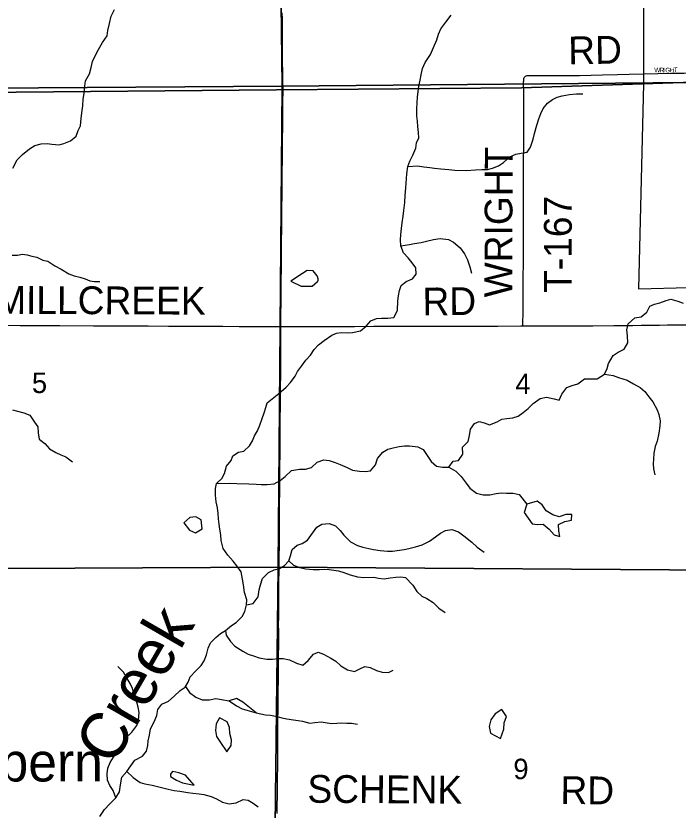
# Model space of a CAD drawing. Extents: x 0 to 1391, y -24 to 440.
# Drawn here: x 416.5 to 443.6, y 299.64 to 332.13 of the extents above; entities that cross this region are included whole.
import ezdxf

# ---------------------------------------------------------------- set-up
doc = ezdxf.new("R2010")
doc.units = 0
for name, color, linetype in [('GM_X_City_Street', 7, 'Continuous'), ('GM_X_City_Street_Text', 7, 'Continuous'), ('GM_X_Corporation', 7, 'Continuous'), ('GM_X_County_Road', 7, 'Continuous'), ('GM_X_County_Road_Text', 7, 'Continuous'), ('GM_X_Minor_Lake', 7, 'Continuous'), ('GM_X_Minor_River', 7, 'Continuous'), ('GM_X_Minor_River_Text', 7, 'Continuous'), ('GM_X_Section', 7, 'Continuous'), ('GM_X_Section_Text', 7, 'Continuous'), ('GM_X_Township', 7, 'Continuous'), ('GM_X_Township_Road', 7, 'Continuous'), ('GM_X_Township_Road_Text', 7, 'Continuous'), ('GM_X_Unincorporated_Text', 7, 'Continuous')]:
    doc.layers.add(name, color=color, linetype=linetype)

msp = doc.modelspace()

# ---------------------------------------------------------------- linework, layer by layer
at = {"layer": 'GM_X_City_Street'}
msp.add_lwpolyline([(442.19, 329.762), (442.767, 329.777), (443.327, 329.783), (443.836, 329.79), (444.271, 329.796), (444.88, 329.802), (445.689, 329.801), (445.987, 329.805), (446.099, 329.813), (446.184, 329.83), (446.255, 329.854), (446.299, 329.876), (446.351, 329.91), (446.408, 329.958), (446.475, 330.031), (446.574, 330.16), (447.022, 330.771), (447.05, 330.799), (447.082, 330.824), (447.146, 330.858)], dxfattribs=at)
at = {"layer": 'GM_X_Corporation'}
msp.add_lwpolyline([(442.179, 333.534), (442.187, 329.348), (441.975, 320.968), (444.035, 321.013)], dxfattribs=at)
at = {"layer": 'GM_X_County_Road'}
for points in [[(415.038, 319.479), (415.24, 319.478), (415.7, 319.473), (416.681, 319.468), (417.464, 319.464), (418.297, 319.459), (419.676, 319.452), (420.559, 319.449), (421.329, 319.451), (421.913, 319.449), (422.746, 319.442), (422.97, 319.442), (423.193, 319.442), (423.628, 319.441), (424.287, 319.437), (424.97, 319.431), (425.641, 319.424), (426.263, 319.417), (427.341, 319.416)], [(427.341, 319.416), (427.518, 319.416), (428.027, 319.418), (428.859, 319.416), (429.717, 319.416), (430.351, 319.421), (431.134, 319.431), (431.793, 319.434), (432.053, 319.434), (432.513, 319.434), (433.419, 319.437), (433.729, 319.436), (434.202, 319.438), (434.985, 319.439), (435.606, 319.438), (436.227, 319.442), (437.16, 319.444), (437.251, 319.445)], [(437.251, 319.445), (437.756, 319.446), (438.378, 319.452), (439.856, 319.454), (440.105, 319.452), (440.962, 319.46), (441.31, 319.463), (441.745, 319.467), (442.093, 319.471), (442.838, 319.48), (443.161, 319.484), (443.533, 319.489), (444.006, 319.488), (444.553, 319.492), (445.087, 319.491), (445.696, 319.493), (446.18, 319.49), (446.553, 319.491), (447.137, 319.491)]]:
    msp.add_lwpolyline(points, dxfattribs=at)
at = {"layer": 'GM_X_Minor_Lake'}
for points in [[(428.826, 321.491), (428.663, 321.699), (428.42, 321.711), (428.227, 321.594), (427.745, 321.278)], [(428.837, 321.256), (428.841, 321.258), (428.844, 321.26), (428.847, 321.263), (428.85, 321.266), (428.852, 321.269), (428.855, 321.272), (428.857, 321.276), (428.86, 321.279), (428.862, 321.283), (428.864, 321.288), (428.865, 321.292), (428.867, 321.297), (428.868, 321.302), (428.869, 321.307), (428.87, 321.312), (428.871, 321.318), (428.871, 321.324), (428.872, 321.33), (428.872, 321.336), (428.872, 321.342), (428.871, 321.348), (428.871, 321.355), (428.87, 321.361), (428.869, 321.368), (428.868, 321.375), (428.867, 321.382), (428.865, 321.389), (428.864, 321.396), (428.862, 321.403), (428.86, 321.411), (428.858, 321.418), (428.855, 321.425), (428.853, 321.432), (428.85, 321.44), (428.847, 321.447), (428.844, 321.455), (428.841, 321.462), (428.837, 321.469), (428.834, 321.476), (428.83, 321.484), (428.826, 321.491)], [(427.745, 321.278), (428.172, 321.073), (428.362, 321.069), (428.621, 321.071), (428.837, 321.256)], [(438.704, 311.326), (438.963, 311.448), (439.23, 311.503), (439.256, 311.73), (439.006, 311.735), (438.73, 311.642), (438.466, 311.723), (438.203, 311.88), (438.04, 312.134), (437.837, 312.274), (437.404, 312.157)], [(437.404, 312.157), (437.297, 311.816), (437.46, 311.578), (437.63, 311.347), (437.85, 311.32), (438.071, 311.338), (438.326, 311.136), (438.527, 310.897), (438.754, 310.831), (438.72, 311.067), (438.704, 311.326)], [(424.128, 311.139), (424.087, 311.519), (423.861, 311.637), (423.617, 311.604), (423.374, 311.397)], [(423.374, 311.397), (423.6, 311.09), (423.849, 310.978), (424.128, 311.139)], [(426.335, 303.617), (425.786, 304.062), (425.522, 304.203), (425.223, 304.113)], [(425.223, 304.113), (425.524, 303.901), (425.766, 303.789), (426.335, 303.617)], [(436.391, 303.762), (436.108, 303.579), (435.929, 303.333), (435.871, 303.054), (435.927, 302.788), (436.334, 302.568)], [(436.334, 302.568), (436.469, 302.951), (436.482, 303.208), (436.578, 303.471), (436.391, 303.762)], [(424.83, 303.419), (424.698, 303.168), (424.67, 302.896), (424.711, 302.645), (424.867, 302.407), (425.133, 302.023)], [(425.133, 302.023), (425.313, 302.277), (425.325, 302.519), (425.253, 302.77), (425.235, 303.013), (425.148, 303.257), (424.83, 303.419)], [(422.922, 301.214), (422.897, 301.211), (422.827, 301.116), (422.826, 301.02)], [(423.79, 300.658), (423.444, 301.074), (423.172, 301.163), (422.922, 301.214)], [(422.826, 301.02), (423.076, 300.863), (423.325, 300.759), (423.79, 300.658)]]:
    msp.add_lwpolyline(points, dxfattribs=at)
at = {"layer": 'GM_X_Minor_River'}
for points in [[(416.381, 325.903), (416.55, 326.235), (416.771, 326.46), (417.053, 326.685), (417.282, 326.819), (417.54, 326.9), (417.776, 326.906), (417.973, 326.874), (418.269, 326.856), (418.467, 326.908), (418.741, 327.019), (418.969, 327.206), (419.054, 327.433), (419.146, 327.629), (419.171, 327.932), (419.203, 328.167), (419.234, 328.447), (419.251, 328.72), (419.29, 328.947), (419.322, 329.257), (419.346, 329.469), (419.507, 329.756), (419.585, 330.013), (419.632, 330.255), (419.747, 330.489), (419.877, 330.746), (420.046, 331.04), (420.23, 331.311), (420.269, 331.523), (420.331, 331.81), (420.401, 332.113), (420.539, 332.385)], [(430.829, 319.435), (431.03, 319.651), (431.26, 319.746), (431.466, 319.758), (431.717, 319.761), (431.969, 319.794), (432.119, 320.072), (432.125, 320.474), (432.151, 320.671), (432.193, 320.89), (432.273, 321.101), (432.466, 321.257), (432.727, 321.367), (432.875, 321.569), (432.871, 321.819), (432.715, 322.027), (432.551, 322.227), (432.356, 322.435), (432.254, 322.725), (432.243, 322.968), (432.254, 323.18), (432.281, 323.43), (432.308, 323.665), (432.351, 323.937), (432.378, 324.172), (432.413, 324.49), (432.433, 324.778), (432.454, 325.088), (432.465, 325.278), (432.502, 325.672), (432.545, 325.967), (432.624, 326.178), (432.743, 326.426), (432.862, 326.72), (432.896, 326.939), (432.983, 327.143), (432.972, 327.355), (432.953, 327.598), (432.934, 327.826), (432.907, 328.039), (432.904, 328.312), (432.916, 328.585), (432.935, 328.797), (432.988, 329.252), (433.046, 329.501), (433.08, 329.72), (433.137, 329.97), (433.248, 330.226), (433.467, 330.548), (433.593, 330.827), (433.728, 331.143), (433.793, 331.377), (433.895, 331.595), (434.09, 331.865), (434.316, 332.157)], [(432.545, 325.967), (432.941, 325.99), (433.192, 325.956), (433.435, 325.921), (433.625, 325.895), (433.891, 325.868), (434.21, 325.839), (434.469, 325.812), (434.94, 325.804), (435.306, 325.836), (435.565, 325.839), (435.794, 325.85), (436, 325.899), (436.246, 325.994), (436.453, 326.127), (436.716, 326.357), (436.954, 326.475), (437.183, 326.516), (437.42, 326.558), (437.553, 326.76), (437.665, 327.084), (437.722, 327.319), (437.819, 327.651), (437.9, 327.915), (437.979, 328.133), (438.082, 328.337), (438.253, 328.554), (438.461, 328.709), (438.653, 328.805), (438.852, 328.862), (439.15, 328.91), (439.44, 328.943), (439.706, 328.938)], [(432.254, 322.725), (432.605, 322.772), (432.812, 322.814), (433.079, 322.855), (433.301, 322.919), (433.591, 322.983), (433.858, 323.023), (434.2, 322.98), (434.404, 322.877), (434.682, 322.645), (434.86, 322.392), (434.978, 322.154), (435.072, 321.865), (435.144, 321.598)], [(416.353, 322.333), (416.566, 322.346), (416.771, 322.375), (416.961, 322.35), (417.158, 322.303), (417.363, 322.256), (417.605, 322.14), (417.802, 322.093), (418.09, 321.909), (418.347, 321.77), (418.665, 321.57), (418.885, 321.492), (419.12, 321.437), (419.332, 321.367), (419.529, 321.29), (419.718, 321.265), (419.931, 321.263)], [(434.212, 313.664), (434.391, 313.911), (434.612, 313.938), (434.792, 314.2), (434.781, 314.489), (435.014, 314.72), (435.056, 314.969), (435.106, 315.226), (435.27, 315.459), (435.461, 315.531), (435.658, 315.475), (435.885, 315.402), (436.192, 315.519), (436.384, 315.637), (436.59, 315.663), (436.834, 315.689), (437.049, 315.754), (437.257, 315.91), (437.457, 316.066), (437.667, 316.274), (437.959, 316.474), (438.212, 316.538), (438.522, 316.457), (438.727, 316.408), (438.838, 316.648), (439.048, 316.926), (439.27, 317.013), (439.492, 317.07), (439.77, 317.285), (440.036, 317.288), (440.287, 317.283), (440.58, 317.476), (440.691, 317.709), (440.747, 317.905), (440.943, 318.235), (441.143, 318.376), (441.397, 318.493), (441.546, 318.749), (441.528, 319.037), (441.501, 319.28), (441.559, 319.537), (441.822, 319.775), (442.081, 319.817), (442.313, 320.002), (442.446, 320.258), (442.638, 320.33), (442.845, 320.387), (443.113, 320.482), (443.304, 320.539), (443.584, 320.458), (443.804, 320.379)], [(419.939, 299.379), (420.126, 299.664), (420.351, 299.903), (420.591, 300.141), (420.74, 300.389), (420.775, 300.677), (420.842, 300.994), (421.043, 301.226), (421.207, 301.451), (421.371, 301.69), (421.678, 301.844), (421.841, 302.046), (421.899, 302.28), (421.917, 302.477), (421.974, 302.711), (422.009, 302.969), (422.159, 303.247), (422.27, 303.51), (422.312, 303.752), (422.468, 303.97), (422.744, 304.101), (422.976, 304.295), (423.223, 304.533), (423.431, 304.673), (423.556, 304.868), (423.629, 305.095), (423.861, 305.341), (424.086, 305.549), (424.211, 305.752), (424.298, 305.986), (424.364, 306.258), (424.459, 306.476), (424.684, 306.7), (424.877, 306.863), (425.077, 306.989), (425.324, 307.197), (425.516, 307.315), (425.764, 307.561), (425.866, 307.764), (425.94, 308.043), (425.951, 308.24), (425.849, 308.538), (425.808, 308.849), (425.774, 309.093), (425.719, 309.39), (425.548, 309.635), (425.398, 309.827), (425.167, 310.074), (424.988, 310.343), (424.895, 310.663), (424.884, 310.906), (424.849, 311.127), (424.815, 311.332), (424.795, 311.552), (424.784, 311.773), (424.75, 312.008), (424.693, 312.252), (424.667, 312.518), (424.664, 312.791), (424.713, 312.995), (424.922, 313.211), (425.032, 313.407), (425.121, 313.709), (425.315, 313.94), (425.379, 314.136), (425.61, 314.277), (425.832, 314.318), (426.064, 314.534), (426.189, 314.752), (426.269, 314.948), (426.394, 315.15), (426.489, 315.384), (426.585, 315.663), (426.658, 315.897), (426.722, 316.108), (426.779, 316.304), (426.987, 316.467), (427.265, 316.683), (427.558, 316.943), (427.737, 317.137), (427.924, 317.392), (428.018, 317.587), (428.19, 317.797), (428.369, 318.044), (428.555, 318.253), (428.711, 318.478), (428.882, 318.672), (429.113, 318.85), (429.429, 319.065), (429.621, 319.145), (429.827, 319.172), (430.086, 319.167), (430.276, 319.179), (430.597, 319.249), (430.829, 319.435)], [(440.58, 317.476), (440.937, 317.416), (441.164, 317.329), (441.512, 317.224), (441.776, 317.083), (442.048, 316.927), (442.243, 316.764), (442.407, 316.549), (442.564, 316.341), (442.741, 316.012), (442.814, 315.821), (442.863, 315.562), (442.852, 315.365), (442.816, 315.055), (442.742, 314.73), (442.655, 314.512), (442.612, 314.247), (442.585, 313.989), (442.574, 313.8), (442.594, 313.602), (442.65, 313.351)], [(416.364, 316.02), (416.568, 315.965), (416.826, 315.894), (417.069, 315.801), (417.264, 315.504), (417.392, 315.313), (417.414, 315.07), (417.458, 314.82), (417.692, 314.636), (417.873, 314.422), (418.131, 314.268), (418.343, 314.176), (418.54, 314.091), (418.82, 313.891)], [(424.713, 312.995), (425.223, 313.009), (425.543, 312.996), (426.038, 312.987), (426.327, 312.974), (426.54, 312.963), (426.784, 312.959), (427.066, 312.992), (427.319, 313.124), (427.52, 313.287), (427.775, 313.526), (428.111, 313.581), (428.355, 313.592), (428.592, 313.648), (428.824, 313.872), (429.108, 313.965), (429.32, 313.946), (429.57, 313.859), (429.767, 313.779), (430.054, 313.653), (430.281, 313.55), (430.562, 313.508), (430.798, 313.496), (431.011, 313.515), (431.221, 313.769), (431.301, 314.018), (431.511, 314.28), (431.726, 314.398), (431.941, 314.462), (432.185, 314.511), (432.406, 314.537), (432.605, 314.542), (432.947, 314.505), (433.165, 314.388), (433.329, 314.15), (433.492, 313.897), (433.71, 313.703), (433.96, 313.668), (434.212, 313.664), (434.506, 313.5), (434.715, 313.284), (434.932, 313.014), (435.081, 312.815), (435.344, 312.605), (435.617, 312.532), (435.898, 312.535), (436.151, 312.591), (436.372, 312.618), (436.57, 312.607), (436.851, 312.609), (437.094, 312.552), (437.404, 312.157)], [(425.94, 308.043), (426.215, 308.091), (426.417, 308.369), (426.46, 308.648), (426.509, 308.86), (426.597, 309.116), (426.837, 309.355), (427.075, 309.465), (427.289, 309.529), (427.497, 309.647), (427.675, 309.841), (427.732, 310.037), (427.812, 310.294), (428.006, 310.48), (428.213, 310.545), (428.428, 310.685), (428.818, 311.209), (429.025, 311.342), (429.323, 311.36), (429.573, 311.272), (429.775, 311.079), (429.916, 310.887), (430.193, 310.616), (430.473, 310.467), (430.692, 310.395), (430.943, 310.338), (431.132, 310.304), (431.413, 310.261), (431.71, 310.233), (431.916, 310.237), (432.198, 310.27), (432.389, 310.297), (432.58, 310.34), (432.855, 310.411), (433.123, 310.497), (433.43, 310.643), (433.677, 310.821), (433.877, 310.969), (434.085, 311.08), (434.344, 311.113), (434.609, 311.017), (434.827, 310.862), (435.158, 310.606), (435.375, 310.39), (435.669, 310.187)], [(427.675, 309.841), (427.855, 309.656), (428.105, 309.568), (428.363, 309.51), (428.659, 309.482), (428.926, 309.485), (429.116, 309.497), (429.322, 309.486), (429.702, 309.434), (429.921, 309.354), (430.186, 309.266), (430.474, 309.178), (430.732, 309.158), (431.144, 309.166), (431.341, 309.125), (431.577, 309.105), (431.821, 309.139), (432.05, 309.166), (432.256, 309.177), (432.446, 309.151), (432.745, 308.842), (432.901, 308.582), (433.11, 308.389), (433.322, 308.301), (433.571, 308.138), (433.81, 307.898), (434.066, 307.72)], [(425.077, 306.989), (425.104, 306.798), (425.282, 306.537), (425.454, 306.345), (425.786, 306.142), (426.012, 306.024), (426.224, 305.952), (426.459, 305.872), (426.763, 305.821), (426.999, 305.817), (427.235, 305.836), (427.433, 305.84), (427.691, 305.79), (427.986, 305.648), (428.243, 305.576), (428.46, 305.761), (428.685, 306.023), (428.876, 306.096), (429.088, 306.024), (429.39, 305.859), (429.594, 305.734), (429.804, 305.548), (430.068, 305.377), (430.356, 305.311), (430.571, 305.414), (430.778, 305.516), (430.998, 305.475), (431.263, 305.356), (431.49, 305.284), (431.748, 305.264), (431.94, 305.36)], [(420.591, 300.141), (420.482, 300.447), (420.341, 300.654), (420.253, 300.868), (420.242, 301.118), (420.261, 301.361), (420.357, 301.587), (420.497, 301.812), (420.646, 302.022), (420.833, 302.314), (420.967, 302.57), (421.245, 302.823), (421.456, 303.1), (421.513, 303.319), (421.541, 303.637), (421.499, 303.858), (421.442, 304.109), (421.325, 304.392), (421.268, 304.613), (421.172, 304.819), (421.017, 305.087), (420.898, 305.279), (420.674, 305.518)], [(423.442, 304.69), (423.611, 304.456), (423.866, 304.254), (424.123, 304.157), (424.427, 304.151), (424.686, 304.206), (424.914, 304.171), (425.223, 304.113)], [(426.335, 303.617), (426.719, 303.542), (426.917, 303.523), (427.189, 303.472), (427.386, 303.415), (427.591, 303.38), (427.856, 303.329), (428.045, 303.31), (428.235, 303.283), (428.53, 303.201), (428.736, 303.219), (428.987, 303.252), (429.245, 303.209), (429.434, 303.182), (429.632, 303.193), (429.83, 303.204), (430.043, 303.192), (430.24, 303.195), (430.475, 303.16)], [(421.043, 301.226), (421.306, 300.979), (421.592, 300.769), (421.781, 300.72), (422.077, 300.662), (422.297, 300.605), (422.509, 300.555), (422.737, 300.498), (422.972, 300.449), (423.215, 300.422), (423.542, 300.363), (423.739, 300.337), (423.997, 300.302), (424.188, 300.283), (424.491, 300.195), (424.71, 300.1), (424.959, 299.967), (425.224, 299.894), (425.514, 299.934), (425.806, 300.073), (426.011, 300.047), (426.215, 299.93), (426.41, 299.774)]]:
    msp.add_lwpolyline(points, dxfattribs=at)
at = {"layer": 'GM_X_Section'}
for points in [[(447.184, 349.582), (447.102, 329.433), (427.403, 329.248), (427.145, 349.502)], [(427.145, 349.502), (427.403, 329.248), (407.447, 329.121), (407.364, 349.38)], [(447.102, 329.433), (447.244, 309.439), (427.24, 309.578), (427.403, 329.248)], [(427.403, 329.248), (427.24, 309.578), (407.8, 309.486), (407.447, 329.121)], [(427.24, 309.578), (427.002, 289.599), (407.817, 289.368), (407.8, 309.486)], [(447.244, 309.439), (447.159, 289.547), (427.002, 289.599), (427.24, 309.578)]]:
    msp.add_lwpolyline(points, close=True, dxfattribs=at)
at = {"layer": 'GM_X_Township'}
for points in [[(366.961, 368.979), (366.895, 354.384), (366.863, 348.93), (366.886, 328.586), (407.375, 328.93), (427.17, 329.098), (437.196, 329.183), (447.101, 329.514), (447.1, 329.807), (447.095, 330.76), (447.22, 339.546), (447.212, 344.406), (447.181, 349.555), (447.172, 350.472), (447.169, 351.314), (447.12, 358.688), (447.049, 369.139)], [(447.101, 329.514), (437.196, 329.183), (427.17, 329.098), (407.375, 328.93)]]:
    msp.add_lwpolyline(points, dxfattribs=at)
at = {"layer": 'GM_X_Township_Road'}
for points in [[(427.426, 329.406), (427.424, 329.537), (427.421, 329.823), (427.412, 330.257), (427.409, 330.605), (427.412, 331.015), (427.41, 331.388), (427.409, 331.549), (427.404, 331.997), (427.401, 332.245)], [(437.279, 329.454), (437.282, 329.534), (437.286, 329.569), (437.301, 329.602), (437.322, 329.633), (437.35, 329.657), (437.383, 329.675), (437.418, 329.686), (437.449, 329.692), (437.479, 329.695), (438.871, 329.683), (439.567, 329.689), (440.039, 329.7), (440.499, 329.712), (441.12, 329.732), (441.592, 329.747), (442.19, 329.762)], [(437.251, 319.445), (437.251, 319.561), (437.251, 319.66), (437.252, 319.896), (437.254, 320.405), (437.26, 321.126), (437.267, 322.331), (437.27, 323.437), (437.272, 324.059), (437.278, 324.643), (437.276, 325.992), (437.276, 326.277), (437.281, 326.675), (437.282, 326.849), (437.284, 327.308), (437.285, 327.768), (437.287, 328.364), (437.28, 329.097), (437.278, 329.284), (437.278, 329.447), (437.279, 329.454)], [(427.341, 319.416), (427.34, 319.524), (427.339, 319.66), (427.344, 319.97), (427.352, 320.343), (427.359, 320.877), (427.359, 321.225), (427.364, 321.871), (427.371, 322.418), (427.373, 322.815), (427.381, 323.511), (427.386, 324.269), (427.394, 324.803), (427.4, 325.487), (427.405, 326.518), (427.412, 326.965), (427.421, 327.711), (427.429, 328.531), (427.432, 329.14), (427.431, 329.206)], [(427.431, 329.206), (427.429, 329.277), (427.426, 329.401), (427.426, 329.406)], [(427.186, 299.506), (427.199, 299.83), (427.205, 300.227), (427.208, 300.575), (427.211, 301.047), (427.214, 301.346), (427.216, 301.967), (427.218, 302.19), (427.221, 302.786), (427.224, 303.22), (427.224, 303.419), (427.228, 303.679), (427.229, 303.866), (427.231, 303.99), (427.236, 304.337), (427.24, 304.585), (427.246, 304.883), (427.249, 305.169), (427.248, 305.553), (427.249, 305.702), (427.251, 305.938), (427.258, 306.41), (427.256, 306.646), (427.255, 306.857), (427.253, 307.328), (427.254, 307.453), (427.255, 307.552), (427.258, 307.8), (427.259, 307.95), (427.26, 308.036), (427.264, 308.496), (427.267, 308.993), (427.269, 309.403), (427.27, 309.474), (427.271, 309.763), (427.275, 309.999), (427.282, 310.471), (427.286, 311.092), (427.289, 311.552), (427.289, 311.775), (427.293, 312.21), (427.298, 312.62), (427.304, 313.204), (427.307, 313.651), (427.313, 314.273), (427.319, 315.478), (427.325, 316.336), (427.325, 316.696), (427.33, 317.031), (427.339, 317.367), (427.343, 317.814), (427.343, 318.162), (427.343, 318.41), (427.345, 318.857), (427.346, 319.168), (427.341, 319.416)]]:
    msp.add_lwpolyline(points, dxfattribs=at)

# ---------------------------------------------------------------- texts
at = {"layer": 'GM_X_City_Street_Text'}
for s, rotation, p in [('W', 0.0336, (442.624, 329.815)), ('R', 0.0243, (442.84, 329.815)), ('I', 0.049, (442.99, 329.815)), ('G', 0.0437, (443.074, 329.815)), ('H', 2.1905, (443.248, 329.815)), ('T', 4.0056, (443.421, 329.822))]:
    msp.add_text(s, height=0.189, rotation=rotation, dxfattribs=at).set_placement(p)
at = {"layer": 'GM_X_County_Road_Text'}
for s, rotation, p in [('MILLCREEK', 359.7606, (415.648, 319.943)), ('RD', 0.4857, (433.143, 319.876))]:
    msp.add_text(s, height=1.1364, rotation=rotation, dxfattribs=at).set_placement(p)
at = {"layer": 'GM_X_Minor_River_Text'}
msp.add_text('Creek', height=1.8934, rotation=60.011, dxfattribs=at).set_placement((420.477, 301.39))
at = {"layer": 'GM_X_Section_Text'}
for s, p in [('5', (417.157, 316.699)), ('4', (436.94, 316.662)), ('9', (436.857, 300.906))]:
    msp.add_text(s, height=0.837, rotation=0, dxfattribs=at).set_placement(p)
at = {"layer": 'GM_X_Township_Road_Text'}
for s, rotation, p in [('RD', 0.9647, (439.112, 330.143)), ('WRIGHT', 89.8286, (436.81, 320.612)), ('T-167', 90, (439.246, 320.796)), ('SCHENK', 359.6587, (428.428, 299.943)), ('RD', 359.5173, (438.78, 299.892))]:
    msp.add_text(s, height=1.1364, rotation=rotation, dxfattribs=at).set_placement(p)
at = {"layer": 'GM_X_Unincorporated_Text'}
msp.add_text('Newbern', height=1.5795, rotation=0, dxfattribs=at).set_placement((411.607, 300.812))

doc.saveas('drawing.dxf')
